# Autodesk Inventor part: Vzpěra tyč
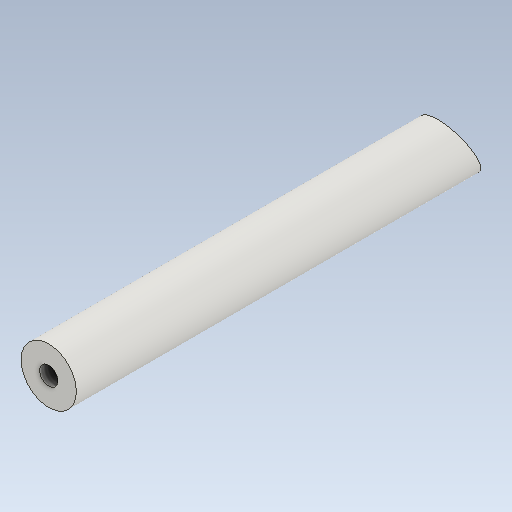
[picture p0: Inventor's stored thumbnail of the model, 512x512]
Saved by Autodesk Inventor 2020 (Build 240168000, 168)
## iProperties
Created: 2025-03
Part Number: Vzpěra tyč
Material: Ocel
Document SubType Name: Modeling
Designer: doma
Density: 7.85 g/cm^3
Appearance: Ocel
Mass: 352.739 g
Surface Area: 102.202 cm^2
Volume: 44.9349 cm^3
Author: doma
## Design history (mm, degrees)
sketch "Náčrt1"
  geometry: C1 r 10 at (0, 0); 1 further point
  constraints: 1 centre point, 1 coincident
  dimensions: "d0" = 20 diameter of C1
extrude "Vysunutí1" new body sketch "Náčrt1" distance "d1" = 150; taper "d2" = 0 deg
sketch "Náčrt2"
  geometry: L1 (-10, 0)-(-10, 150) reference; L2 (-10, 0)-(23.135, 15.451); L3 (-10, 0)-(26.561, 0); L4 (23.135, 15.451)-(28.917, -16.425); L5 (28.917, -16.425)-(-18.388, -18.473); L6 (10, 0)-(-10, 0) reference; L7 (-18.388, -18.473)-(-10, 0); 1 further point
  constraints: 10 end point, 1 equal length, 1 horizontal, 1 point on line
  dimensions: "d3" = 25 deg angle of L3 L2
extrude "Vysunutí2" cut sketch "Náčrt2" stored distance "d4" = 130; taper "d5" = 0 deg
sketch "Náčrt3"
  geometry: 2 further points
hole "Díra1" sketch "Náčrt3" at (0, 0) diameter "d6" = 6.647; stored, may be unused: countersink angle "d10" = 90 deg, drill point angle "d12" = 118 deg; dims "d7" = 15, "d8" = 4, "d9" = 2, "d11" = 20.2
node "Těleso1"
